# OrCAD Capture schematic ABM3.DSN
size A
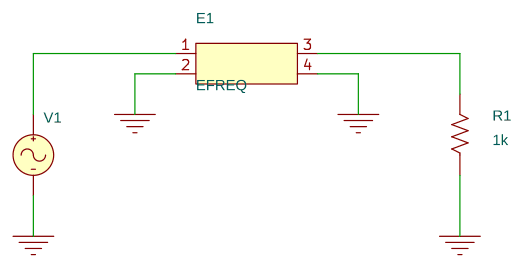
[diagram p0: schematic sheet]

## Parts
E1  EFREQ
R1  1k  [AX/RC05]
V1  VAC

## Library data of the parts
E1 = EFREQ
R1 = R
V1 = VAC

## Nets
0: E1.2(IN-) E1.4(OUT-) R1.1 V1.2(-)
N00112: E1.1(IN+) V1.1(+)
N00119: E1.3(OUT+) R1.2
